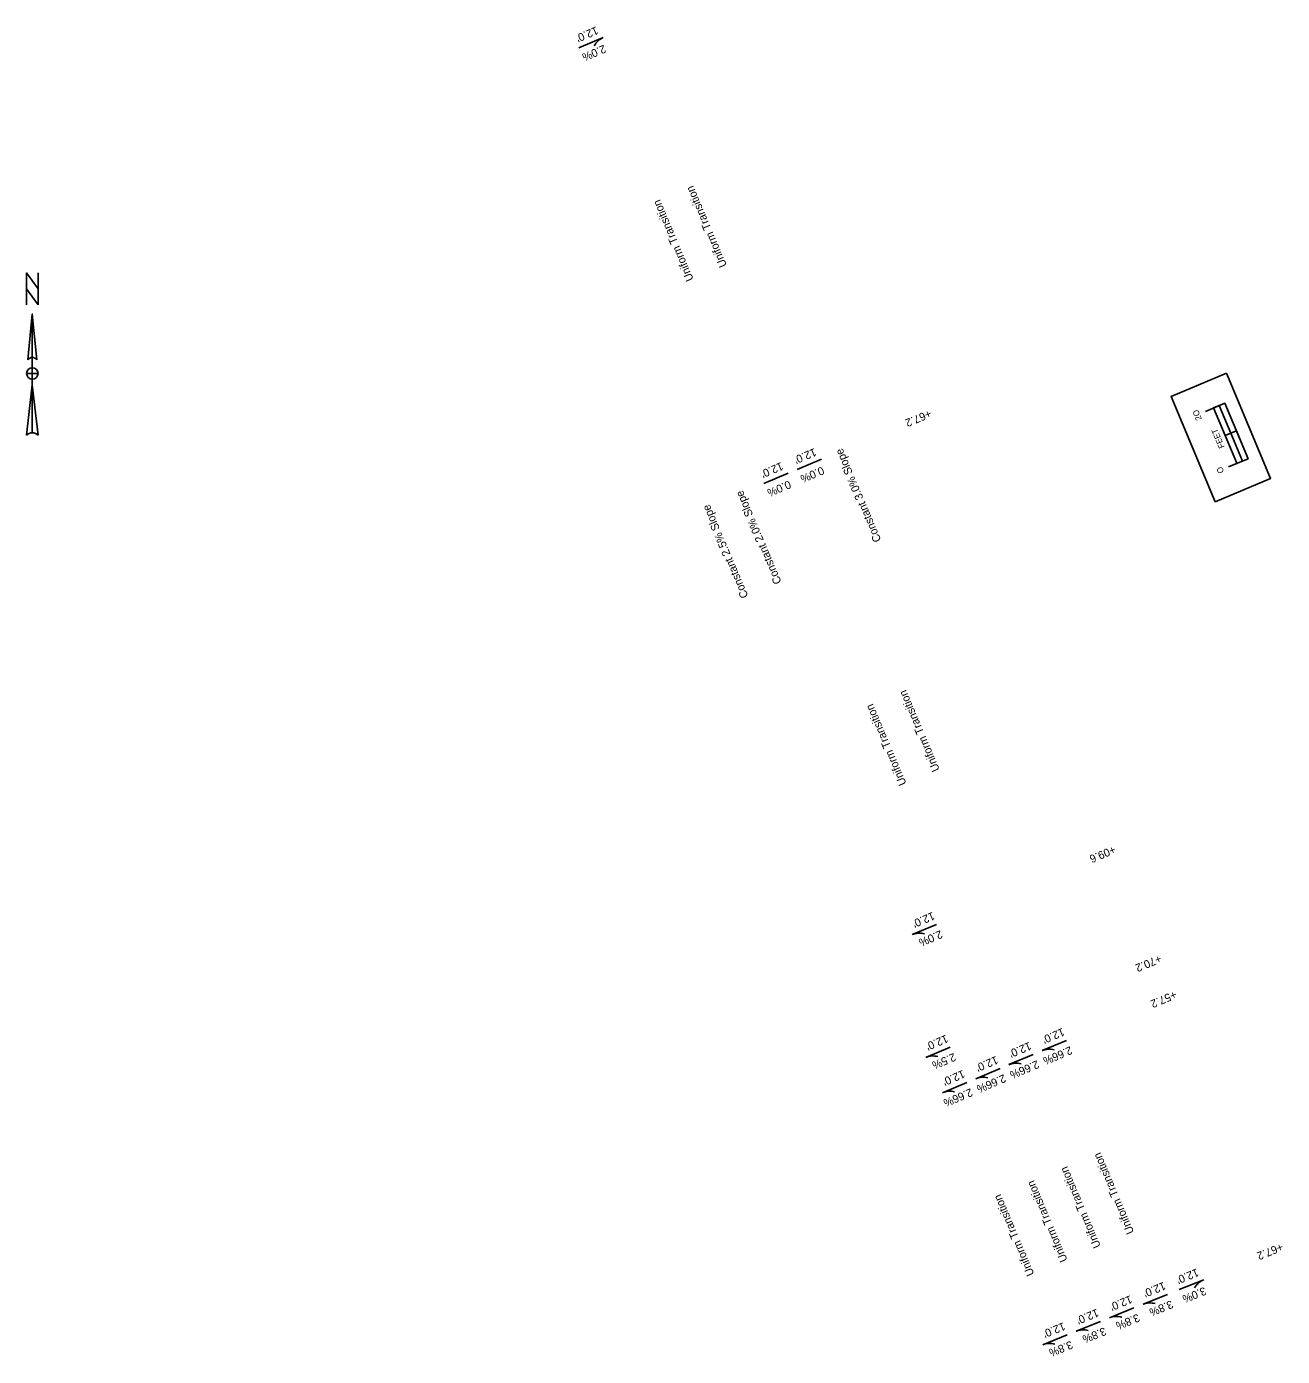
# Model space of a CAD drawing. Extents: x 20505303 to 20506906, y 7965397 to 7979025.
# Drawn here: x 20505970.8 to 20506388.8, y 7975517.9 to 7975960.7 of the extents above; entities that cross this region are included whole.
import ezdxf

# ---------------------------------------------------------------- set-up
doc = ezdxf.new("R2010")
doc.units = 0
doc.layers.add('_CIVIL_CONSTRUCTION', color=7, linetype='Continuous')
doc.layers.add('Alignment', color=7, linetype='Continuous')

msp = doc.modelspace()

# ---------------------------------------------------------------- linework, layer by layer
at = {"layer": '_CIVIL_CONSTRUCTION'}
for p, q in [((20505972.68, 7975864.98), (20505974.2, 7975849.77)), ((20505972.68, 7975864.98), (20505972.68, 7975825.43)), ((20505971.16, 7975849.77), (20505971.16, 7975849.77)), ((20505971.22, 7975849.91), (20505971.5, 7975850.23)), ((20505970.78, 7975824.67), (20505972.68, 7975841.4)), ((20505972.68, 7975843.31), (20505972.68, 7975843.31))]:
    msp.add_line(p, q, dxfattribs=at)
msp.add_lwpolyline([(20505974.58, 7975868.03), (20505970.78, 7975873.35), (20505970.78, 7975878.67), (20505974.58, 7975873.35)], close=True, dxfattribs=at)
for points in [[(20505970.78, 7975868.03), (20505970.78, 7975878.67), (20505974.58, 7975873.35), (20505974.58, 7975878.67)], [(20505971.16, 7975849.77), (20505972.68, 7975864.98), (20505972.68, 7975850.53)], [(20505972.68, 7975843.31), (20505972.68, 7975845.21), (20505970.78, 7975845.21)], [(20505974.58, 7975845.21), (20505972.68, 7975845.21), (20505972.68, 7975847.11)], [(20505972.68, 7975825.43), (20505972.68, 7975841.4), (20505974.58, 7975824.67)]]:
    msp.add_lwpolyline(points, dxfattribs=at)
for centre, radius, start, end in [((20505972.68, 7975848.63), 1.9, 90.0204, 143.1257), ((20505972.68, 7975848.63), 1.9, 36.8481, 90.0218), ((20505972.68, 7975845.21), 1.9, 90, 180), ((20505972.68, 7975845.21), 1.9, 180, 270), ((20505972.68, 7975845.21), 1.9, 0, 90), ((20505972.68, 7975845.21), 1.9, 270, 360), ((20505972.68, 7975822.68), 2.76, 89.9894, 133.619), ((20505972.68, 7975822.67), 2.76, 46.4021, 90.0006)]:
    msp.add_arc(centre, radius, start, end, dxfattribs=at)
at = {"layer": 'Alignment'}
for p, q in [((20506154.62, 7975953.62), (20506162.71, 7975957.03)), ((20506373.45, 7975826.04), (20506369.76, 7975824.49)), ((20506373.45, 7975826.04), (20506369.76, 7975824.49)), ((20506227.25, 7975813.21), (20506235.33, 7975816.62)), ((20506216.2, 7975808.55), (20506224.28, 7975811.96)), ((20506273.67, 7975661.74), (20506265.59, 7975658.33)), ((20506316.89, 7975623.11), (20506308.81, 7975619.7)), ((20506278.13, 7975620.86), (20506270.05, 7975617.45)), ((20506305.83, 7975618.44), (20506297.75, 7975615.03)), ((20506294.78, 7975613.77), (20506286.69, 7975610.36)), ((20506283.72, 7975609.11), (20506275.64, 7975605.7)), ((20506354.44, 7975540.13), (20506362.57, 7975543.41)), ((20506350.5, 7975538.54), (20506342.37, 7975535.25)), ((20506339.37, 7975534.05), (20506331.24, 7975530.76)), ((20506328.25, 7975529.55), (20506320.11, 7975526.27)), ((20506317.12, 7975525.06), (20506308.99, 7975521.78))]:
    msp.add_line(p, q, dxfattribs=at)
for points in [[(20506366.42, 7975802.48), (20506351.71, 7975837.51), (20506370.15, 7975845.26), (20506384.86, 7975810.22)], [(20506366.42, 7975802.48), (20506351.71, 7975837.51), (20506370.15, 7975845.26), (20506384.86, 7975810.22)], [(20506371.59, 7975825.26), (20506367.72, 7975834.48), (20506365.89, 7975833.71), (20506369.76, 7975824.49)], [(20506377.32, 7975816.82), (20506373.45, 7975826.04), (20506371.59, 7975825.26), (20506375.46, 7975816.04)]]:
    msp.add_lwpolyline(points, close=True, dxfattribs=at)
for points in [[(20506370.87, 7975814.11), (20506377.32, 7975816.82), (20506369.58, 7975835.26), (20506363.12, 7975832.55)], [(20506373.63, 7975815.27), (20506365.89, 7975833.71)]]:
    msp.add_lwpolyline(points, dxfattribs=at)
for centre, start, end in [((20506165.1, 7975951.35), 112.8763, 151.0793), ((20506267.99, 7975652.65), 74.6732, 112.8763), ((20506311.2, 7975614.02), 74.6748, 112.8779), ((20506272.44, 7975611.77), 74.6732, 112.8763), ((20506300.15, 7975609.35), 74.6748, 112.8779), ((20506289.09, 7975604.69), 74.6748, 112.8779), ((20506278.04, 7975600.02), 74.6748, 112.8779), ((20506364.88, 7975537.69), 111.9795, 150.1825), ((20506344.68, 7975529.54), 73.7765, 111.9795), ((20506333.55, 7975525.05), 73.7765, 111.9795), ((20506322.42, 7975520.56), 73.7765, 111.9795), ((20506311.29, 7975516.06), 73.7765, 111.9795)]:
    msp.add_arc(centre, 6.16, start, end, dxfattribs=at)

# ---------------------------------------------------------------- texts
for s, height, rotation, p in [("12.0'", 2.664, 202.979, (20506160.35, 7975960.81)), ('2.0%', 2.664, 202.979, (20506162.92, 7975954.7)), ('Uniform Transition', 2.664, 112.8763, (20506203.92, 7975881.16)), ('Uniform Transition', 2.664, 112.8763, (20506192.85, 7975876.51)), ('+67.2', 2.664, 202.8779, (20506271.27, 7975833.23)), ('2O', 2, 112.7854, (20506362, 7975830.04)), ('FEET', 2, 112.7854, (20506369.6, 7975820.75)), ("12.0'", 2.664, 202.979, (20506232.98, 7975820.4)), ('Constant 3.0% Slope', 2.664, 112.8763, (20506255.29, 7975789.66)), ("12.0'", 2.664, 202.979, (20506221.92, 7975815.73)), ('0.0%', 2.664, 202.979, (20506235.55, 7975814.29)), ('O', 2, 112.7854, (20506369.4, 7975812.42)), ('0.0%', 2.664, 202.979, (20506224.5, 7975809.63)), ('Constant 2.0% Slope', 2.664, 112.8763, (20506222.12, 7975775.67)), ('Constant 2.5% Slope', 2.664, 112.8763, (20506211.06, 7975771)), ('Uniform Transition', 2.664, 112.8763, (20506274.77, 7975713.24)), ('Uniform Transition', 2.664, 112.8763, (20506263.7, 7975708.6)), ('+09.6', 2.664, 202.8779, (20506332.6, 7975688.05)), ("12.0'", 2.664, 202.979, (20506272.36, 7975665.96)), ('2.0%', 2.664, 202.979, (20506274.94, 7975659.86)), ('+70.2', 2.664, 202.8779, (20506347.86, 7975651.73)), ('+57.2', 2.664, 202.8779, (20506352.92, 7975639.75)), ("12.0'", 2.664, 202.9806, (20506315.58, 7975627.32)), ("12.0'", 2.664, 202.979, (20506276.82, 7975625.08)), ('2.5%', 2.664, 202.979, (20506279.39, 7975618.97)), ("12.0'", 2.664, 202.9806, (20506304.52, 7975622.66)), ('2.66%', 2.664, 202.9806, (20506318.15, 7975621.22)), ("12.0'", 2.664, 202.9806, (20506293.46, 7975617.99)), ('2.66%', 2.664, 202.9806, (20506307.09, 7975616.55)), ("12.0'", 2.664, 202.9806, (20506282.41, 7975613.33)), ('2.66%', 2.664, 202.9806, (20506296.04, 7975611.89)), ('2.66%', 2.664, 202.9806, (20506284.98, 7975607.22)), ('Uniform Transition', 2.664, 112.7854, (20506339.44, 7975559.21)), ('Uniform Transition', 2.664, 112.7854, (20506328.37, 7975554.56)), ('Uniform Transition', 2.664, 112.7854, (20506317.31, 7975549.91)), ('Uniform Transition', 2.664, 112.7854, (20506306.25, 7975545.27)), ('+67.2', 2.664, 201.9795, (20506388.39, 7975555.72)), ("12.0'", 2.664, 202.0822, (20506360.28, 7975547.22)), ("12.0'", 2.664, 202.0822, (20506349.26, 7975542.77)), ('3.0%', 2.664, 202.0822, (20506362.76, 7975541.08)), ("12.0'", 2.664, 202.0822, (20506338.13, 7975538.28)), ('3.8%', 2.664, 202.0822, (20506351.73, 7975536.63)), ("12.0'", 2.664, 202.0822, (20506327, 7975533.79)), ('3.8%', 2.664, 202.0822, (20506340.61, 7975532.14)), ("12.0'", 2.664, 202.0822, (20506315.87, 7975529.3)), ('3.8%', 2.664, 202.0822, (20506329.48, 7975527.65)), ('3.8%', 2.664, 202.0822, (20506318.35, 7975523.16))]:
    msp.add_text(s, height=height, rotation=rotation, dxfattribs=at).set_placement(p)

doc.saveas('drawing.dxf')
